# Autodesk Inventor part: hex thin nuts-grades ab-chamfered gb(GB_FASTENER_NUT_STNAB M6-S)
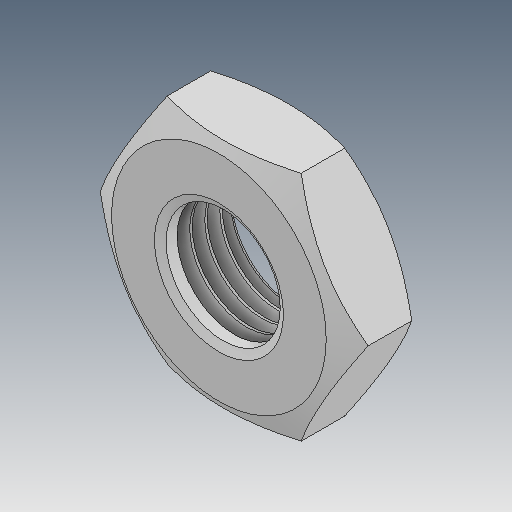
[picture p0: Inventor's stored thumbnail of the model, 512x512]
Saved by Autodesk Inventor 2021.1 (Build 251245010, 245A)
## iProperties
Created: 2019-05
Part Number: hex thin nuts-grades ab-chamfered gb(GB_FASTENER_NUT_STNAB M6-S)
Material: Ogólny
Document SubType Name: Modeling
Designer: user
Density: 1 g/cm^3
Appearance: Domyślna
Author: user
Revision Number: ÈÎºÎ
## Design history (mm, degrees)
feature "ÊäÈë1"
node "Bryła1"
